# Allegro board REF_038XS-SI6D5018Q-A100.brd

Outline 581.66 x 429.26 mm; copper layers: TOP, L02_GND, L03_DPS, L04_GND, L05_DPS, L06_GND, L07_DPS, L08_GND, L09_DPS, L10_GND, L11_DPS, L12_GND, L13_SIGNAL, L14_GND, L15_SIGNAL, L16_GND, L17_SIGNAL, L18_GND, L19_SIGNAL, L20_GND, L21_SIGNAL, L22_GND, L23_SIGNAL, L24_GND, L25_SIGNAL, L26_GND, L27_SIGNAL, L28_GND, L29_SIGNAL, L30_GND, L31_SIGNAL, L32_GND, L33_SIGNAL, L34_GND, L35_DPS, L36_UDB, L37_GND, BOTTOM. Coordinates in mm from the lower left corner of the outline.

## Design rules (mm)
net group D231_MCB1_E: nets D231_MCB1_E+ D231_MCB1_E-
net group D231_MCB1_EE: nets D231_MCB1_EE+ D231_MCB1_EE-
net group D231_MCB1_F: nets D231_MCB1_F+ D231_MCB1_F-
net group D231_MCB1_FF: nets D231_MCB1_FF+ D231_MCB1_FF-
net group D231_MCB1_G: nets D231_MCB1_G+ D231_MCB1_G-
net group D231_MCB1_GG: nets D231_MCB1_GG+ D231_MCB1_GG-
net group D231_MCB1_H: nets D231_MCB1_H+ D231_MCB1_H-
net group D231_MCB1_HH: nets D231_MCB1_HH+ D231_MCB1_HH-
net group D232_MCB1_E: nets D232_MCB1_E+ D232_MCB1_E-
net group D232_MCB1_EE: nets D232_MCB1_EE+ D232_MCB1_EE-
net group D232_MCB1_F: nets D232_MCB1_F+ D232_MCB1_F-
net group D232_MCB1_FF: nets D232_MCB1_FF+ D232_MCB1_FF-
net group D232_MCB1_G: nets D232_MCB1_G+ D232_MCB1_G-
net group D232_MCB1_GG: nets D232_MCB1_GG+ D232_MCB1_GG-
net group D232_MCB1_H: nets D232_MCB1_H+ D232_MCB1_H-
net group D232_MCB1_HH: nets D232_MCB1_HH+ D232_MCB1_HH-
net group D431_MCB1_AA: nets D431_MCB1_AA+ D431_MCB1_AA-
net group D431_MCB1_BB: nets D431_MCB1_BB+ D431_MCB1_BB-
net group D431_MCB1_CC: nets D431_MCB1_CC+ D431_MCB1_CC-
net group D431_MCB1_DD: nets D431_MCB1_DD+ D431_MCB1_DD-
net group D432_MCB1_A: nets D432_MCB1_A+ D432_MCB1_A-
net group D432_MCB1_AA: nets D432_MCB1_AA+ D432_MCB1_AA-
net group D432_MCB1_B: nets D432_MCB1_B+ D432_MCB1_B-
net group D432_MCB1_BB: nets D432_MCB1_BB+ D432_MCB1_BB-
net group D432_MCB1_C: nets D432_MCB1_C+ D432_MCB1_C-
net group D432_MCB1_CC: nets D432_MCB1_CC+ D432_MCB1_CC-
net group D432_MCB1_D: nets D432_MCB1_D+ D432_MCB1_D-
net group D432_MCB1_DD: nets D432_MCB1_DD+ D432_MCB1_DD-
net group DIFFPAIR900: nets D21401 D21403
net group DIFFPAIR904: nets D10601 D10603
net group AWG: nets S1_AWG_2SHARE+ S1_AWG_2SHARE- S2_AWG_2SHARE+ S2_AWG_2SHARE- S3_AWG_2SHARE+ S3_AWG_2SHARE- S4_AWG_2SHARE+ S4_AWG_2SHARE- S5_AWG_2SHARE+ S5_AWG_2SHARE- S6_AWG_2SHARE+ S6_AWG_2SHARE- S7_AWG_2SHARE+ S7_AWG_2SHARE- S8_AWG_2SHARE+ S8_AWG_2SHARE-
net group ETH-1: nets D10907 D10909 D10912 D10914 D11307 D11309 D11312 D11314 D11708 D11710 D11711 D11713 D12108 D12110 D12111 D12113
net group ETH-2: nets D10905 D10910 D10911 D10916 D11305 D11310 D11311 D11316 D11706 D11709 D11712 D11715 D12106 D12109 D12112 D12115
net group ETH-3: nets D10906 D10908 D10913 D10915 D11306 D11308 D11313 D11315 D11705 D11707 D11714 D11716 D12105 D12107 D12114 D12116
net group MIPI1: nets D21601 D21603 D21901 D21903 D22109 D22111
net group MIPI2: nets D21602 D21604 D21902 D21904 D22110 D22112
net group MIPI3: nets D21605 D21607 D21905 D21907 D22113 D22115
net group MIPI4: nets D21606 D21608 D21906 D21908 D22114 D22116
net group MIPI5: nets D10801 D10803 D12009 D12011 D12901 D12903
net group MIPI6: nets D10802 D10804 D12010 D12012 D12902 D12904
net group MIPI7: nets D10805 D10807 D12013 D12015 D12905 D12907
net group MIPI8: nets D10806 D10808 D12014 D12016 D12906 D12908
net group MIPI SWITCH: nets S1_OUT_RX0_CH0_ABC_CASE+ S1_OUT_RX0_CH0_ABC_CASE- S1_OUT_RX0_CH1_ABC_CASE+ S1_OUT_RX0_CH1_ABC_CASE- S1_OUT_RX0_CH2_ABC_CASE+ S1_OUT_RX0_CH2_ABC_CASE-
net group MIPI SWITCH1: nets S2_OUT_RX0_CH0_ABC_CASE+ S2_OUT_RX0_CH0_ABC_CASE- S2_OUT_RX0_CH1_ABC_CASE+ S2_OUT_RX0_CH1_ABC_CASE- S2_OUT_RX0_CH2_ABC_CASE+ S2_OUT_RX0_CH2_ABC_CASE- S3_OUT_RX0_CH0_ABC_CASE+ S3_OUT_RX0_CH0_ABC_CASE- S3_OUT_RX0_CH1_ABC_CASE+ S3_OUT_RX0_CH1_ABC_CASE- S3_OUT_RX0_CH2_ABC_CASE+ S3_OUT_RX0_CH2_ABC_CASE- S4_OUT_RX0_CH0_ABC_CASE+ S4_OUT_RX0_CH0_ABC_CASE- S4_OUT_RX0_CH1_ABC_CASE+ S4_OUT_RX0_CH1_ABC_CASE- S4_OUT_RX0_CH2_ABC_CASE+ S4_OUT_RX0_CH2_ABC_CASE- S5_OUT_RX0_CH0_ABC_CASE+ S5_OUT_RX0_CH0_ABC_CASE- S5_OUT_RX0_CH1_ABC_CASE+ S5_OUT_RX0_CH1_ABC_CASE- S5_OUT_RX0_CH2_ABC_CASE+ S5_OUT_RX0_CH2_ABC_CASE- S6_OUT_RX0_CH0_ABC_CASE+ S6_OUT_RX0_CH0_ABC_CASE- S6_OUT_RX0_CH1_ABC_CASE+ S6_OUT_RX0_CH1_ABC_CASE- S6_OUT_RX0_CH2_ABC_CASE+ S6_OUT_RX0_CH2_ABC_CASE- S7_OUT_RX0_CH0_ABC_CASE+ S7_OUT_RX0_CH0_ABC_CASE- S7_OUT_RX0_CH1_ABC_CASE+ S7_OUT_RX0_CH1_ABC_CASE- S7_OUT_RX0_CH2_ABC_CASE+ S7_OUT_RX0_CH2_ABC_CASE- S8_OUT_RX0_CH0_ABC_CASE+ S8_OUT_RX0_CH0_ABC_CASE- S8_OUT_RX0_CH1_ABC_CASE+ S8_OUT_RX0_CH1_ABC_CASE- S8_OUT_RX0_CH2_ABC_CASE+ S8_OUT_RX0_CH2_ABC_CASE-

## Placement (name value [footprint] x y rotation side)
2SA1  SHORT  [DEFAULT_SHORT_SMALL]  265.71 251.64 180 top
2SA2  SHORT  [DEFAULT_SHORT_SMALL]  265.71 252.15 180 top
2SA7  SHORT  [DEFAULT_SHORT_SMALL]  264.03 245.86 90 top
2SA8  SHORT  [DEFAULT_SHORT_SMALL]  265.3 245.86 90 top
2SA9  SHORT  [DEFAULT_SHORT_SMALL]  266.07 238 180 top
2SA10  SHORT  [DEFAULT_SHORT_SMALL]  266.07 237.49 180 top
2SA15  SHORT  [DEFAULT_SHORT_SMALL]  277.49 250.16 90 top
2SA16  SHORT  [DEFAULT_SHORT_SMALL]  276.98 250.16 90 top
2SA17  SHORT  [DEFAULT_SHORT_SMALL]  273.21 238.53 0 top
2SA18  SHORT  [DEFAULT_SHORT_SMALL]  273.21 237.92 0 top
2SA19  SHORT  [DEFAULT_SHORT_SMALL]  264.08 243.68 270 top
2SA20  SHORT  [DEFAULT_SHORT_SMALL]  263.49 243.68 270 top
2SA21  SHORT  [DEFAULT_SHORT_SMALL]  279.27 250.18 90 top
2SA22  SHORT  [DEFAULT_SHORT_SMALL]  280.54 250.2 90 top
2SA23  SHORT  [DEFAULT_SHORT_SMALL]  273.41 237.52 270 top
2SA24  SHORT  [DEFAULT_SHORT_SMALL]  274.06 237.52 270 top
3SA1  SHORT  [DEFAULT_SHORT_SMALL]  305.71 251.64 180 top
3SA2  SHORT  [DEFAULT_SHORT_SMALL]  305.71 252.15 180 top
3SA7  SHORT  [DEFAULT_SHORT_SMALL]  304.03 245.86 90 top
3SA8  SHORT  [DEFAULT_SHORT_SMALL]  305.3 245.86 90 top
3SA9  SHORT  [DEFAULT_SHORT_SMALL]  306.07 238 180 top
3SA10  SHORT  [DEFAULT_SHORT_SMALL]  306.07 237.49 180 top
3SA15  SHORT  [DEFAULT_SHORT_SMALL]  317.49 250.16 90 top
3SA16  SHORT  [DEFAULT_SHORT_SMALL]  316.98 250.16 90 top
3SA17  SHORT  [DEFAULT_SHORT_SMALL]  313.21 238.53 0 top
3SA18  SHORT  [DEFAULT_SHORT_SMALL]  313.21 237.92 0 top
3SA19  SHORT  [DEFAULT_SHORT_SMALL]  304.08 243.68 270 top
3SA20  SHORT  [DEFAULT_SHORT_SMALL]  303.49 243.68 270 top
3SA21  SHORT  [DEFAULT_SHORT_SMALL]  319.27 250.18 90 top
3SA22  SHORT  [DEFAULT_SHORT_SMALL]  320.54 250.2 90 top
3SA23  SHORT  [DEFAULT_SHORT_SMALL]  313.41 237.52 270 top
3SA24  SHORT  [DEFAULT_SHORT_SMALL]  314.06 237.52 270 top
4SA1  SHORT  [DEFAULT_SHORT_SMALL]  345.71 251.64 180 top
4SA2  SHORT  [DEFAULT_SHORT_SMALL]  345.71 252.15 180 top
4SA7  SHORT  [DEFAULT_SHORT_SMALL]  344.03 245.86 90 top
4SA8  SHORT  [DEFAULT_SHORT_SMALL]  345.3 245.86 90 top
4SA9  SHORT  [DEFAULT_SHORT_SMALL]  346.07 238 180 top
4SA10  SHORT  [DEFAULT_SHORT_SMALL]  346.07 237.49 180 top
4SA15  SHORT  [DEFAULT_SHORT_SMALL]  357.49 250.16 90 top
4SA16  SHORT  [DEFAULT_SHORT_SMALL]  356.98 250.16 90 top
4SA17  SHORT  [DEFAULT_SHORT_SMALL]  353.21 238.53 0 top
4SA18  SHORT  [DEFAULT_SHORT_SMALL]  353.21 237.92 0 top
4SA19  SHORT  [DEFAULT_SHORT_SMALL]  344.08 243.68 270 top
4SA20  SHORT  [DEFAULT_SHORT_SMALL]  343.49 243.68 270 top
4SA21  SHORT  [DEFAULT_SHORT_SMALL]  359.27 250.18 90 top
4SA22  SHORT  [DEFAULT_SHORT_SMALL]  360.54 250.2 90 top
4SA23  SHORT  [DEFAULT_SHORT_SMALL]  353.41 237.52 270 top
4SA24  SHORT  [DEFAULT_SHORT_SMALL]  354.06 237.52 270 top
5SA1  SHORT  [DEFAULT_SHORT_SMALL]  236.06 191.36 0 top
5SA2  SHORT  [DEFAULT_SHORT_SMALL]  236.06 191.87 0 top
5SA7  SHORT  [DEFAULT_SHORT_SMALL]  223.4 185.16 90 top
5SA8  SHORT  [DEFAULT_SHORT_SMALL]  223.91 185.16 90 top
5SA9  SHORT  [DEFAULT_SHORT_SMALL]  234.24 174.5 270 top
5SA10  SHORT  [DEFAULT_SHORT_SMALL]  235.03 174.5 270 top
5SA15  SHORT  [DEFAULT_SHORT_SMALL]  239.49 193.83 90 top
5SA16  SHORT  [DEFAULT_SHORT_SMALL]  238.98 193.83 90 top
5SA17  SHORT  [DEFAULT_SHORT_SMALL]  235.98 191.77 0 top
5SA18  SHORT  [DEFAULT_SHORT_SMALL]  235.98 192.46 0 top
5SA19  SHORT  [DEFAULT_SHORT_SMALL]  224.08 183.68 270 top
5SA20  SHORT  [DEFAULT_SHORT_SMALL]  223.49 183.68 270 top
5SA21  SHORT  [DEFAULT_SHORT_SMALL]  234.54 193.95 0 top
5SA22  SHORT  [DEFAULT_SHORT_SMALL]  234.54 195.43 0 top
5SA23  SHORT  [DEFAULT_SHORT_SMALL]  233.04 174.51 270 top
5SA24  SHORT  [DEFAULT_SHORT_SMALL]  234.32 174.51 270 top
6SA1  SHORT  [DEFAULT_SHORT_SMALL]  276.06 191.36 0 top
6SA2  SHORT  [DEFAULT_SHORT_SMALL]  276.06 191.87 0 top
6SA7  SHORT  [DEFAULT_SHORT_SMALL]  263.4 185.16 90 top
6SA8  SHORT  [DEFAULT_SHORT_SMALL]  263.91 185.16 90 top
6SA9  SHORT  [DEFAULT_SHORT_SMALL]  274.24 174.5 270 top
6SA10  SHORT  [DEFAULT_SHORT_SMALL]  275.03 174.5 270 top
6SA15  SHORT  [DEFAULT_SHORT_SMALL]  279.49 193.83 90 top
6SA16  SHORT  [DEFAULT_SHORT_SMALL]  278.98 193.83 90 top
6SA17  SHORT  [DEFAULT_SHORT_SMALL]  275.98 191.77 0 top
6SA18  SHORT  [DEFAULT_SHORT_SMALL]  275.98 192.46 0 top
6SA19  SHORT  [DEFAULT_SHORT_SMALL]  264.08 183.68 270 top
6SA20  SHORT  [DEFAULT_SHORT_SMALL]  263.49 183.68 270 top
6SA21  SHORT  [DEFAULT_SHORT_SMALL]  274.54 193.95 0 top
6SA22  SHORT  [DEFAULT_SHORT_SMALL]  274.54 195.43 0 top
6SA23  SHORT  [DEFAULT_SHORT_SMALL]  273.04 174.51 270 top
6SA24  SHORT  [DEFAULT_SHORT_SMALL]  274.32 174.51 270 top
7SA1  SHORT  [DEFAULT_SHORT_SMALL]  316.06 191.36 0 top
7SA2  SHORT  [DEFAULT_SHORT_SMALL]  316.06 191.87 0 top
7SA7  SHORT  [DEFAULT_SHORT_SMALL]  303.4 185.16 90 top
7SA8  SHORT  [DEFAULT_SHORT_SMALL]  303.91 185.16 90 top
7SA9  SHORT  [DEFAULT_SHORT_SMALL]  314.24 174.5 270 top
7SA10  SHORT  [DEFAULT_SHORT_SMALL]  315.03 174.5 270 top
7SA15  SHORT  [DEFAULT_SHORT_SMALL]  319.49 193.83 90 top
7SA16  SHORT  [DEFAULT_SHORT_SMALL]  318.98 193.83 90 top
7SA17  SHORT  [DEFAULT_SHORT_SMALL]  315.98 191.77 0 top
7SA18  SHORT  [DEFAULT_SHORT_SMALL]  315.98 192.46 0 top
7SA19  SHORT  [DEFAULT_SHORT_SMALL]  304.08 183.68 270 top
7SA20  SHORT  [DEFAULT_SHORT_SMALL]  303.49 183.68 270 top
7SA21  SHORT  [DEFAULT_SHORT_SMALL]  314.54 193.95 0 top
7SA22  SHORT  [DEFAULT_SHORT_SMALL]  314.54 195.43 0 top
7SA23  SHORT  [DEFAULT_SHORT_SMALL]  313.04 174.51 270 top
7SA24  SHORT  [DEFAULT_SHORT_SMALL]  314.32 174.51 270 top
8SA1  SHORT  [DEFAULT_SHORT_SMALL]  356.06 191.36 0 top
8SA2  SHORT  [DEFAULT_SHORT_SMALL]  356.06 191.87 0 top
8SA7  SHORT  [DEFAULT_SHORT_SMALL]  343.4 185.16 90 top
8SA8  SHORT  [DEFAULT_SHORT_SMALL]  343.91 185.16 90 top
8SA9  SHORT  [DEFAULT_SHORT_SMALL]  354.24 174.5 270 top
8SA10  SHORT  [DEFAULT_SHORT_SMALL]  355.03 174.5 270 top
8SA15  SHORT  [DEFAULT_SHORT_SMALL]  359.49 193.83 90 top
8SA16  SHORT  [DEFAULT_SHORT_SMALL]  358.98 193.83 90 top
8SA17  SHORT  [DEFAULT_SHORT_SMALL]  355.98 191.77 0 top
8SA18  SHORT  [DEFAULT_SHORT_SMALL]  355.98 192.46 0 top
8SA19  SHORT  [DEFAULT_SHORT_SMALL]  344.08 183.68 270 top
8SA20  SHORT  [DEFAULT_SHORT_SMALL]  343.49 183.68 270 top
8SA21  SHORT  [DEFAULT_SHORT_SMALL]  354.54 193.95 0 top
8SA22  SHORT  [DEFAULT_SHORT_SMALL]  354.54 195.43 0 top
8SA23  SHORT  [DEFAULT_SHORT_SMALL]  353.04 174.51 270 top
8SA24  SHORT  [DEFAULT_SHORT_SMALL]  354.32 174.51 270 top
BD5  BD120-1.5A-S4-MU  [FB0402]  543.47 239.79 270 bottom
BD9  BD120-1.5A-S4-MU  [FB0402]  224.66 243.83 270 bottom
BD21  BD120-1.5A-S4-MU  [FB0402]  222.95 232.36 0 bottom
BD1721  BD120-1.5A-S4-MU  [FB0402]  543.47 226.84 270 bottom
BD1722  BD120-1.5A-S4-MU  [FB0402]  543.09 213.5 270 bottom
BD1723  BD120-1.5A-S4-MU  [FB0402]  543.09 199.41 270 bottom
BD1728  BD120-1.5A-S4-MU  [FB0402]  229.83 271.82 270 bottom
BD1729  BD120-1.5A-S4-MU  [FB0402]  236.97 270.94 270 bottom
BDB5  BD120-1.5A-S4-MU  [FB0402]  211.03 246.46 0 bottom
BDB6  BD120-1.5A-S4-MU  [FB0402]  211.03 234.89 0 bottom
BGA234-11X11-P0.65  REF-CODE-SOCKET  [SOCKET_CODE]  3.67 430.51 0 top
C262  0.1U-16-X7S-S2-MU  [C0201]  224.41 232.06 270 bottom
C264  NC/10U-16-X7R-S8-SS  [C0805]  227.48 269.95 90 bottom
C267  33P-50-N-S2-MU  [C0201]  236.23 224.18 270 bottom
C268  33P-50-N-S2-MU  [C0201]  235.23 224.18 270 bottom
C270  NC/10U-16-X7R-S8-SS  [C0805]  224.95 259 0 bottom
C271  12P-50-N-S4-MU  [C0402]  232.95 267.19 180 bottom
C272  12P-50-N-S4-MU  [C0402]  230.93 267.19 0 bottom
C278  1U-10-X7S-S4-TDK  [C0402]  232.87 289.3 0 bottom
C279  1U-10-X7S-S4-TDK  [C0402]  232.87 288.11 0 bottom
C280  0.1U-16-X-S4-MU  [C0402]  232.87 286.91 0 bottom
C281  0.1U-16-X-S4-MU  [C0402]  232.87 285.72 0 bottom
C282  1U-10-X7S-S4-TDK  [C0402]  238.7 282.67 270 bottom
C283  0.1U-16-X-S4-MU  [C0402]  237.54 282.67 270 bottom
C284  1U-10-X7S-S4-TDK  [C0402]  237.62 294.04 90 bottom
C285  0.1U-16-X-S4-MU  [C0402]  238.81 294.04 90 bottom
C286  0.1U-16-X-S4-MU  [C0402]  233.82 293.54 180 bottom
C288  1000P-50-X7R-S2-MU  [C0201]  233.49 291.76 270 bottom
C289  0.1U-16-X-S4-MU  [C0402]  231.21 291 270 bottom
C290  NC/0.1U-16-X7R-S4-TY  [C0402]  224.35 292.22 180 bottom
C298  0.1U-16-X7S-S2-MU  [C0201]  222.95 288.84 90 bottom
C299  0.1U-16-X7S-S2-MU  [C0201]  220.02 293.16 180 bottom
C300  0.1U-16-X-S4-MU  [C0402]  220.67 287.06 270 bottom
C301  1U-10-X7S-S4-TDK  [C0402]  219.51 287.06 270 bottom
C302  10P-50-N-S2-MU  [C0201]  214.98 243.61 0 bottom
C309  10P-50-N-S2-MU  [C0201]  214.98 255.18 0 bottom
C310  10P-50-N-S2-MU  [C0201]  213.69 255.18 180 bottom
C318  10P-50-N-S2-MU  [C0201]  211.94 255.18 0 bottom
C320  10P-50-N-S2-MU  [C0201]  213.69 243.61 180 bottom
C332  2.2U-16-X7R-S6-TY  [C0603]  109.1 226.65 270 bottom
C333  0.1U-16-X-S4-MU  [C0402]  107.7 226.83 270 bottom
C334  10U-16-X7R-S8-SS  [C0805]  100.08 226.53 90 bottom
C335  0.1U-16-X-S4-MU  [C0402]  101.74 226.35 90 bottom
C336  4.7U-25-X7R-S8-TY  [C0805]  87.58 240.29 270 bottom
C337  0.1U-16-X-S4-MU  [C0402]  87.6 237.74 180 bottom
C338  4.7U-25-X7R-S8-TY  [C0805]  106 240.29 270 bottom
C339  0.1U-16-X-S4-MU  [C0402]  106.03 237.74 180 bottom
C400  2.2U-10-X-S4-MU  [C0402]  540.94 239.82 90 bottom
C401  0.1U-16-X-S4-MU  [C0402]  542.2 239.82 90 bottom
C402  4.7U-6.3-X-S4-MU  [C0402]  523.51 152.12 0 bottom
C403  22U-16-X5R-SA-SS  [C1206]  520.12 149.58 90 bottom
C404  10U-25-X-S6-MU  [C0603]  519.86 146.58 180 bottom
C405  1U-10-X7S-S4-TDK  [C0402]  520.37 145.26 180 bottom
C406  0.1U-16-X-S4-MU  [C0402]  90.42 287.53 180 bottom
C407  2.2U-10-X-S4-MU  [C0402]  82.6 288.09 270 bottom
C408  0.1U-16-X-S4-MU  [C0402]  83.74 288.09 270 bottom
C409  0.1U-16-X-S4-MU  [C0402]  73.71 296.14 0 bottom
C410  0.1U-16-X-S4-MU  [C0402]  503.58 221.92 270 bottom
C411  0.1U-16-X-S4-MU  [C0402]  493.55 229.97 0 bottom
C412  2.2U-10-X-S4-MU  [C0402]  502.43 221.92 270 bottom
C413  0.1U-16-X-S4-MU  [C0402]  510.25 221.35 180 bottom
C415  0.1U-16-X-S4-MU  [C0402]  90.42 273.81 180 bottom
C416  2.2U-10-X-S4-MU  [C0402]  82.6 274.38 270 bottom
C417  0.1U-16-X-S4-MU  [C0402]  73.71 282.43 0 bottom
C475  4.7U-6.3-X-S4-MU  [C0402]  225.86 265.11 270 bottom
C476  1U-10-X7S-S4-TDK  [C0402]  219 268.25 90 bottom
C477  10U-25-X-S6-MU  [C0603]  220.32 268.76 90 bottom
C478  22U-16-X5R-SA-SS  [C1206]  223.32 268.5 0 bottom
C894  0.1U-16-X-S4-MU  [C0402]  542.2 226.87 90 bottom
C895  2.2U-10-X-S4-MU  [C0402]  540.94 226.87 90 bottom
C910  0.1U-16-X-S4-MU  [C0402]  83.74 274.38 270 bottom
C922  0.1U-16-X-S4-MU  [C0402]  213.16 246.46 0 bottom
C923  0.1U-16-X-S4-MU  [C0402]  213.16 234.89 0 bottom
C924  10P-50-N-S2-MU  [C0201]  211.94 243.61 0 bottom
C955  0.1U-16-X-S4-MU  [C0402]  90.42 260.1 180 bottom
C956  2.2U-10-X-S4-MU  [C0402]  82.6 260.66 270 bottom
C957  0.1U-16-X-S4-MU  [C0402]  73.71 268.71 0 bottom
C958  0.1U-16-X-S4-MU  [C0402]  83.74 260.66 270 bottom
C983  0.1U-16-X-S4-MU  [C0402]  541.82 213.53 90 bottom
C984  2.2U-10-X-S4-MU  [C0402]  540.55 213.53 90 bottom
C985  0.1U-16-X-S4-MU  [C0402]  541.82 199.44 90 bottom
C986  2.2U-10-X-S4-MU  [C0402]  540.55 199.44 90 bottom
C1066  0.01U-10-X7R-S2-YA  [C0201]  244.98 274.19 0 bottom
C1067  0.01U-10-X7R-S2-YA  [C0201]  246.33 274.19 180 bottom
C1074  0.1U-16-X7S-S2-MU  [C0201_MINI]  229.58 270.27 180 bottom
C1077  0.1U-16-X7S-S2-MU  [C0201_MINI]  236.72 269.49 180 bottom
C1080  0.1U-16-X7S-S2-MU  [C0201_MINI]  242.99 269.49 180 bottom
C1081  0.1U-16-X7S-S2-MU  [C0201_MINI]  243.8 273.3 180 bottom
C1082  0.1U-16-X-S4-MU  [C0402]  503.58 203.76 270 bottom
C1083  0.1U-16-X-S4-MU  [C0402]  248.15 224.79 0 bottom
C1085  2.2U-10-X-S4-MU  [C0402]  493.55 211.81 0 bottom
CA1  0.1U-16-X-S4-MU  [C0402]  205.72 237.49 0 bottom
CA2  10U-25-X7R-SA  [C1206]  205.72 240.03 0 bottom
CA7  10U-25-X7R-SA  [C1206]  245.12 281.69 0 bottom
CA8  0.1U-16-X-S4-MU  [C0402]  245.12 279.65 0 bottom
CA19  470U-25-E-S10.4X10.4  [EC_10P3X10_S]  189.66 230.89 90 bottom
CA20  10U-25-X7R-SA  [C1206]  216.67 281.69 0 bottom
CA21  0.1U-16-X-S4-MU  [C0402]  216.67 279.65 0 bottom
CA22  10U-25-X7R-SA  [C1206]  222.76 277.62 0 bottom
CA23  0.1U-16-X-S4-MU  [C0402]  222.76 275.59 0 bottom
CA24  10U-25-X7R-SA  [C1206]  216.67 277.62 0 bottom
CA25  0.1U-16-X-S4-MU  [C0402]  216.67 275.59 0 bottom
CA26  10U-25-X7R-SA  [C1206]  235.18 277.62 0 bottom
CA27  0.1U-16-X-S4-MU  [C0402]  235.18 275.59 0 bottom
CA34  10U-25-X7R-SA  [C1206]  245.12 277.62 0 bottom
CA35  0.1U-16-X-S4-MU  [C0402]  245.12 275.59 0 bottom
CA36  0.1U-16-X-S4-MU  [C0402]  228.85 275.59 0 bottom
CA37  10U-25-X7R-SA  [C1206]  228.85 277.62 0 bottom
CB1  0.1U-25-X-S6  [C0603]  416.81 133.35 0 bottom
CB2  10U-25-X7R-SA  [C1206]  416.81 130.81 0 bottom
CB3  0.1U-25-X-S6  [C0603]  560.07 133.35 0 bottom
CB4  10U-25-X7R-SA  [C1206]  560.07 130.81 0 bottom
CB5  0.1U-25-X-S6  [C0603]  560.07 295.91 180 bottom
CB6  10U-25-X7R-SA  [C1206]  560.07 298.45 180 bottom
CB7  0.1U-25-X-S6  [C0603]  424.16 290.83 180 bottom
CB8  10U-25-X7R-SA  [C1206]  424.16 293.37 180 bottom
CB9  0.1U-25-X-S6  [C0603]  164.85 133.35 0 bottom
CB10  10U-25-X7R-SA  [C1206]  164.85 130.81 0 bottom
CB11  0.1U-25-X-S6  [C0603]  157.46 290.83 180 bottom
CB12  10U-25-X7R-SA  [C1206]  157.46 293.37 180 bottom
CB13  0.1U-25-X-S6  [C0603]  21.59 133.35 0 bottom
CB14  10U-25-X7R-SA  [C1206]  21.59 130.81 0 bottom
CB15  0.1U-25-X-S6  [C0603]  21.59 295.91 180 bottom
CB16  10U-25-X7R-SA  [C1206]  21.59 298.45 180 bottom
CC1  0.1U-16-X7S-S2-MU  [C0201]  230.19 246.91 180 bottom
CC2  0.1U-16-X7S-S2-MU  [C0201]  230.5 250.48 90 bottom
CC3  0.1U-16-X7S-S2-MU  [C0201]  228.87 245.61 180 bottom
CC4  0.1U-16-X7S-S2-MU  [C0201]  230.19 246.26 180 bottom
CC5  0.1U-16-X7S-S2-MU  [C0201]  231.16 246.56 90 bottom
CC6  0.1U-16-X7S-S2-MU  [C0201]  228.87 244.96 180 bottom
CC7  0.1U-16-X7S-S2-MU  [C0201]  232.14 244.96 0 bottom
CC8  0.1U-16-X7S-S2-MU  [C0201]  230.5 243.97 270 bottom
CC9  0.1U-16-X7S-S2-MU  [C0201]  231.16 243.97 270 bottom
CC12  0.1U-16-X7S-S2-MU  [C0201]  229.86 244.62 270 bottom
CC13  0.1U-16-X7S-S2-MU  [C0201]  228.24 241.05 180 bottom
CC14  0.1U-16-X7S-S2-MU  [C0201]  231.46 245.61 0 bottom
CC15  0.1U-16-X7S-S2-MU  [C0201]  230.19 245.61 180 bottom
CC16  0.1U-16-X7S-S2-MU  [C0201]  230.84 244.96 180 bottom
CC70  0.1U-16-X7S-S2-MU  [C0201]  232.46 242.67 270 bottom
CC71  0.1U-16-X7S-S2-MU  [C0201]  235.38 243 0 bottom
CC73  0.1U-16-X7S-S2-MU  [C0201]  227.91 242.68 90 bottom
CC84  0.1U-16-X7S-S2-MU  [C0201]  233.11 250.48 90 bottom
CC85  0.1U-16-X7S-S2-MU  [C0201]  231.15 250.48 90 bottom
CC86  0.1U-16-X7S-S2-MU  [C0201]  232.46 250.48 90 bottom
CC87  0.1U-16-X7S-S2-MU  [C0201]  232.14 246.26 180 bottom
CC88  0.1U-16-X7S-S2-MU  [C0201]  233.11 244 270 bottom
CC89  0.1U-16-X7S-S2-MU  [C0201]  227.91 244.66 270 bottom
CC90  0.1U-16-X7S-S2-MU  [C0201]  231.8 250.48 90 bottom
CC91  0.1U-16-X7S-S2-MU  [C0201]  234.06 243.65 0 bottom
CC92  0.1U-16-X7S-S2-MU  [C0201]  232.45 244 270 bottom
CC96  0.1U-16-X7S-S2-MU  [C0201]  231.51 247.56 180 bottom
CC101  0.1U-16-X7S-S2-MU  [C0201]  230.84 240.4 0 bottom
CC103  0.1U-16-X7S-S2-MU  [C0201]  231.81 242.02 90 bottom
CC105  0.1U-16-X7S-S2-MU  [C0201]  232.46 240.72 270 bottom
CC107  0.1U-16-X7S-S2-MU  [C0201]  232.76 241.7 0 bottom
CC112  0.1U-16-X7S-S2-MU  [C0201]  235.06 250.48 90 bottom
CC130  0.1U-16-X7S-S2-MU  [C0201]  228.24 241.7 180 bottom
CC133  1U-6.3-X7T-S2-MU  [C0201]  227.26 238.78 270 bottom
CC134  NC/0.1U-10-X7R-S2-MU  [C0201]  227.91 238.78 270 bottom
CC182  0.1U-16-X7S-S2-MU  [C0201]  226.61 250.48 90 bottom
CC194  0.1U-16-X7S-S2-MU  [C0201]  231.49 243 180 bottom
CC202  0.1U-16-X7S-S2-MU  [C0201]  226.28 245.61 180 bottom
CC203  0.1U-16-X7S-S2-MU  [C0201]  229.86 239.42 270 bottom
CC204  0.1U-16-X7S-S2-MU  [C0201]  230.51 239.42 270 bottom
CC205  0.1U-16-X7S-S2-MU  [C0201]  231.16 239.42 270 bottom
CC208  0.1U-16-X7S-S2-MU  [C0201]  227.57 246.26 180 bottom
CC209  0.1U-16-X7S-S2-MU  [C0201]  228.23 247.56 180 bottom
CC210  0.1U-16-X7S-S2-MU  [C0201]  229.53 240.41 180 bottom
CC211  0.1U-16-X7S-S2-MU  [C0201]  230.5 242.02 90 bottom
CC212  0.1U-16-X7S-S2-MU  [C0201]  229.53 241.06 180 bottom
CC213  0.1U-16-X7S-S2-MU  [C0201]  231.16 242.02 90 bottom
CC215  0.1U-16-X7S-S2-MU  [C0201]  231.81 239.42 90 bottom
CC216  0.1U-16-X7S-S2-MU  [C0201]  228.56 238.78 270 bottom
CD1  0.1U-16-X7S-S2-MU  [C0201]  295.73 296.3 90 top
CD2  0.1U-16-X7S-S2-MU  [C0201]  465.17 278.08 90 top
CON1  MS-PWR-CONN-30P-V3-SI6D70  [CONN_15X2_100MIL_PH_MS_V2]  24.74 150.36 90 top
CSDPS303  V93K_CSDPS_DPS32  [PG_VG93K_PF_DPS32_G1D303]  327.66 46.99 0 top
CSDPS307  V93K_CSDPS_DPS32  [PG_VG93K_PF_DPS32_G1D307]  401.32 46.99 0 top
CSDPS310  V93K_CSDPS_DPS32  [PG_VG93K_PF_DPS32_G2D310]  401.32 361.95 0 top
CSDPS314  V93K_CSDPS_DPS32  [PG_VG93K_PF_DPS32_G2D314]  327.66 361.95 0 top
CSDPS319  V93K_CSDPS_DPS32  [PG_VG93K_PF_DPS32_G3D319]  180.34 46.99 0 top
CSDPS323  V93K_CSDPS_DPS32  [PG_VG93K_PF_DPS32_G3D323]  254 46.99 0 top
CSDPS426  V93K_CSDPS  [PG_VG93K_PF_DPS32_G8D426]  254 361.95 0 top
CSDPS430  V93K_CSDPS  [PG_VG93K_PF_DPS32_G8D430]  180.34 361.95 0 top
D101  V93K_CH  [PG_VG93K_F_G1D101]  327.66 97.79 0 top
D102  V93K_CH  [PG_VG93K_F_G1D102]  327.66 77.47 0 top
D103  V93K_CH  [PG_VG93K_F_G1D103]  327.66 57.15 0 top
D104  V93K_CH  [PG_VG93K_F_G1D104]  327.66 36.83 0 top
D105  V93K_CH  [PG_VG93K_F_G1D105]  401.32 97.79 0 top
D106  V93K_CH  [PG_VG93K_F_G1D106]  401.32 77.47 0 top
D107  V93K_CH  [PG_VG93K_F_G1D107]  401.32 57.15 0 top
D108  V93K_CH  [PG_VG93K_F_G1D108]  401.32 36.83 0 top
D109  V93K_CH  [PG_VG93K_F_G2D109]  401.32 331.47 0 top
D110  V93K_CH  [PG_VG93K_F_G2D110]  401.32 351.79 0 top
D111  V93K_CH  [PG_VG93K_F_G2D111]  401.32 372.11 0 top
D112  V93K_CH  [PG_VG93K_F_G2D112]  401.32 392.43 0 top
D113  V93K_CH  [PG_VG93K_F_G2D113]  327.66 331.47 0 top
D114  V93K_CH  [PG_VG93K_F_G2D114]  327.66 351.79 0 top
D115  V93K_CH  [PG_VG93K_F_G2D115]  327.66 372.11 0 top
D116  V93K_CH  [PG_VG93K_F_G2D116]  327.66 392.43 0 top
D117  V93K_CH  [PG_VG93K_F_G3D117]  180.34 97.79 0 top
D118  V93K_CH  [PG_VG93K_F_G3D118]  180.34 77.47 0 top
D119  V93K_CH  [PG_VG93K_F_G3D119]  180.34 57.15 0 top
D120  V93K_CH  [PG_VG93K_F_G3D120]  180.34 36.83 0 top
D121  V93K_CH  [PG_VG93K_F_G3D121]  254 97.79 0 top
D122  V93K_CH  [PG_VG93K_F_G3D122]  254 77.47 0 top
D123  V93K_CH  [PG_VG93K_F_G3D123]  254 57.15 0 top
D124  V93K_CH  [PG_VG93K_F_G3D124]  254 36.83 0 top
D125  V93K_CH  [PG_VG93K_F_G4D125]  33.02 97.79 0 top
D126  V93K_CH  [PG_VG93K_F_G4D126]  33.02 77.47 0 top
D127  V93K_CH  [PG_VG93K_F_G4D127]  33.02 57.15 0 top
D128  V93K_CH  [PG_VG93K_F_G4D128]  33.02 36.83 0 top
D129  V93K_CH  [PG_VG93K_F_G4D129]  106.68 97.79 0 top
D130  V93K_CH  [PG_VG93K_F_G4D130]  106.68 77.47 0 top
D131  V93K_CH  [PG_VG93K_F_G4D131]  106.68 57.15 0 top
D132  V93K_CH  [PG_VG93K_F_G4D132]  106.68 36.83 0 top
D201  V93K_CH  [PG_VG93K_F_G5D201]  474.98 97.79 0 top
D202  V93K_CH  [PG_VG93K_F_G5D202]  474.98 77.47 0 top
D203  V93K_CH  [PG_VG93K_F_G5D203]  474.98 57.15 0 top
D204  V93K_CH  [PG_VG93K_F_G5D204]  474.98 36.83 0 top
D205  V93K_CH  [PG_VG93K_F_G5D205]  548.64 97.79 0 top
D206  V93K_CH  [PG_VG93K_F_G5D206]  548.64 77.47 0 top
D207  V93K_CH  [PG_VG93K_F_G5D207]  548.64 57.15 0 top
D208  V93K_CH  [PG_VG93K_F_G5D208]  548.64 36.83 0 top
D209  V93K_CH  [PG_VG93K_F_G6D209]  548.64 331.47 0 top
D210  V93K_CH  [PG_VG93K_F_G6D210]  548.64 351.79 0 top
D211  V93K_CH  [PG_VG93K_F_G6D211]  548.64 372.11 0 top
D212  V93K_CH  [PG_VG93K_F_G6D212]  548.64 392.43 0 top
D213  V93K_CH  [PG_VG93K_F_G6D213]  474.98 331.47 0 top
D214  V93K_CH  [PG_VG93K_F_G6D214]  474.98 351.79 0 top
D215  V93K_CH  [PG_VG93K_F_G6D215]  474.98 372.11 0 top
D216  V93K_CH  [PG_VG93K_F_G6D216]  474.98 392.43 0 top
D217  V93K_CH  [PG_VG93K_F_G7D217]  106.68 331.47 0 top
D218  V93K_CH  [PG_VG93K_F_G7D218]  106.68 351.79 0 top
D219  V93K_CH  [PG_VG93K_F_G7D219]  106.68 372.11 0 top
D220  V93K_CH  [PG_VG93K_F_G7D220]  106.68 392.43 0 top
D221  V93K_CH  [PG_VG93K_F_G7D221]  33.02 331.47 0 top
D222  V93K_CH  [PG_VG93K_F_G7D222]  33.02 351.79 0 top
D223  V93K_CH  [PG_VG93K_F_G7D223]  33.02 372.11 0 top
D224  V93K_CH  [PG_VG93K_F_G7D224]  33.02 392.43 0 top
D225  V93K_CH_ND  [PG_VG93K_F_G8D225_ND]  254 331.47 0 top
D226/D626  V93K_PS1600 HD  [PG_VG93K_F_HSM_G8D226_626_ND]  254 351.79 0 top
D227  V93K_CH  [PG_VG93K_F_G8D227]  254 372.11 0 top
D228  V93K_CH  [PG_VG93K_F_G8D228]  254 392.43 0 top
D229  V93K_CH_ND  [PG_VG93K_F_G8D229_ND]  180.34 331.47 0 top
D230/D630  V93K_PS1600 HD  [PG_VG93K_F_HSM_G8D230_630_ND]  180.34 351.79 0 top
D231  V93K_CH  [PG_VG93K_F_G8D231]  180.34 372.11 0 top
D232  V93K_CH  [PG_VG93K_F_G8D232]  180.34 392.43 0 top
D325  V93K_CH  [PG_VG93K_F_G4D325]  33.02 87.63 0 top
D326  V93K_CH  [PG_VG93K_F_G4D326]  33.02 67.31 0 top
D327  V93K_CH  [PG_VG93K_F_G4D327]  33.02 46.99 0 top
D328  V93K_CH  [PG_VG93K_F_G4D328]  33.02 26.67 0 top
D329  V93K_CH  [PG_VG93K_F_G4D329]  106.68 87.63 0 top
D330  V93K_CH  [PG_VG93K_F_G4D330]  106.68 67.31 0 top
D331  V93K_CH  [PG_VG93K_F_G4D331]  106.68 46.99 0 top
D332  V93K_CH  [PG_VG93K_F_G4D332]  106.68 26.67 0 top
D409  V93K_CH  [PG_VG93K_F_G6D409]  548.64 341.63 0 top
D410  V93K_CH  [PG_VG93K_F_G6D410]  548.64 361.95 0 top
D411  V93K_CH  [PG_VG93K_F_G6D411]  548.64 382.27 0 top
D412  V93K_CH  [PG_VG93K_F_G6D412]  548.64 402.59 0 top
D413  V93K_CH  [PG_VG93K_F_G6D413]  474.98 341.63 0 top
D414  V93K_CH  [PG_VG93K_F_G6D414]  474.98 361.95 0 top
D415  V93K_CH  [PG_VG93K_F_G6D415]  474.98 382.27 0 top
D416  V93K_CH  [PG_VG93K_F_G6D416]  474.98 402.59 0 top
D417  V93K_CH  [PG_VG93K_F_G7D417]  106.68 341.63 0 top
D418  V93K_CH  [PG_VG93K_F_G7D418]  106.68 361.95 0 top
D419  V93K_CH  [PG_VG93K_F_G7D419]  106.68 382.27 0 top
D420  V93K_CH  [PG_VG93K_F_G7D420]  106.68 402.59 0 top
D421  V93K_CH  [PG_VG93K_F_G7D421]  33.02 341.63 0 top
D422  V93K_CH  [PG_VG93K_F_G7D422]  33.02 361.95 0 top
D423  V93K_CH  [PG_VG93K_F_G7D423]  33.02 382.27 0 top
D424  V93K_CH  [PG_VG93K_F_G7D424]  33.02 402.59 0 top
D425  V93K_CH_ND  [PG_VG93K_F_G8D425_ND]  254 341.63 0 top
D427  V93K_CH  [PG_VG93K_F_G8D427]  254 382.27 0 top
D428  V93K_CH  [PG_VG93K_F_G8D428]  254 402.59 0 top
D429  V93K_CH_ND  [PG_VG93K_F_G8D429_ND]  180.34 341.63 0 top
D431  V93K_CH  [PG_VG93K_F_G8D431]  180.34 382.27 0 top
D432  V93K_CH  [PG_VG93K_F_G8D432]  180.34 402.59 0 top
DPS1  V93K_DPS  [PG_VG93K_F_G1DPS1]  401.32 16.51 0 top
DPS2  V93K_DPS  [PG_VG93K_F_G2DPS2]  327.66 412.75 0 top
DPS3  V93K_DPS  [PG_VG93K_F_G3DPS3]  254 16.51 0 top
DPS8  V93K_DPS  [PG_VG93K_F_G8DPS8]  180.34 412.75 0 top
FD1  -  [FD_040_V2]  10.16 129.54 0 top
FD2  -  [FD_040_V2]  11.43 298.45 0 top
FD3  -  [FD_040_V2]  157.48 298.45 0 top
FD4  -  [FD_040_V2]  157.48 130.81 0 top
FD5  -  [FD_040_V2]  424.18 298.45 0 top
FD6  -  [FD_040_V2]  424.18 130.81 0 top
FD7  -  [FD_040_V2]  570.23 298.45 0 top
FD8  -  [FD_040_V2]  570.23 130.81 0 top
FD9  -  [FD_040_V2]  10.16 129.54 180 bottom
FD10  -  [FD_040_V2]  11.43 298.45 180 bottom
FD11  -  [FD_040_V2]  157.48 298.45 180 bottom
FD12  -  [FD_040_V2]  157.48 130.81 180 bottom
FD13  -  [FD_040_V2]  424.18 298.45 180 bottom
FD14  -  [FD_040_V2]  424.18 130.81 180 bottom
FD15  -  [FD_040_V2]  570.23 298.45 180 bottom
FD16  -  [FD_040_V2]  570.23 130.81 180 bottom
H1  M3-HOLE  [M3_NPTH169]  158.75 241.3 0 top
H2  M3-HOLE  [M3_NPTH169]  158.75 187.96 0 top
H3  M3-HOLE  [M3_NPTH169]  422.91 241.3 0 top
H4  M3-HOLE  [M3_NPTH169]  422.91 187.96 0 top
J1  HDR-2X1-M  [JP_2P_100]  10.78 152.9 180 top
J2  HDR-2X1-M  [JP_2P_100]  14.16 152.9 180 top
JP1  A2001WV0-4PS  [CONN_S4X1_2MM_JWT]  100.37 260.08 90 top
K2  UA2-5NJ-A-V3  [RL_NECUA2_5V_V3]  119.04 248.1 90 bottom
K3  UA2-5NJ-A-V3  [RL_NECUA2_5V_V3]  112.69 248.1 90 bottom
K4  UA2-5NJ-A-V3  [RL_NECUA2_5V_V3]  106.34 248.1 90 bottom
K5  UA2-5NJ-A-V3  [RL_NECUA2_5V_V3]  99.99 248.1 90 bottom
K6  UA2-5NJ-A-V3  [RL_NECUA2_5V_V3]  93.64 248.1 90 bottom
K7  UA2-5NJ-A-V3  [RL_NECUA2_5V_V3]  87.29 248.1 90 bottom
K29  G6K-2F-Y-5V-A  [RL_G6K2F-Y_5V_OMRON]  231.94 258.56 90 bottom
K32  G6K-2F-Y-5V-A  [RL_G6K2F-Y_5V_OMRON]  235.73 231.79 270 bottom
K34  G6K-2P-Y5VDC-A  [RL_OMRONG6K2PY_5V]  166.88 269.24 90 bottom
K39  UA2-5NE-A-V3  [RL_NECUA2_5V_V3]  224.66 224.54 180 bottom
K96  EC2-5NJ  [RL_NECEC2_10P_5V]  203.76 229.39 0 bottom
K107  G6K-2P-Y5VDC-A  [RL_OMRONG6K2PY_5V]  166.88 281.43 90 bottom
K109  G6K-2P-Y5VDC-A  [RL_OMRONG6K2PY_5V]  166.88 293.62 90 bottom
K110  G6K-2P-Y5VDC-A  [RL_OMRONG6K2PY_5V]  176.53 293.62 90 bottom
K111  G6K-2P-Y5VDC-A  [RL_OMRONG6K2PY_5V]  186.18 293.62 90 bottom
K112  G6K-2P-Y5VDC-A  [RL_OMRONG6K2PY_5V]  195.83 293.62 90 bottom
K113  MFS-E1T05G-A  [RL_MFS-E1T-G_5V]  245.11 221.36 0 bottom
LDB1  LDG-2-S8  [LED_0805]  40.96 298.45 0 top
LOGO1  LOGO_SR_SigmaStar  [LOGO_SR_SIGMASTAR]  29.16 434.98 0 top
LOGO2  -  [LOGO_KT_KSMT]  81.21 434.37 0 top
LRB1  330-1-S6  [R0603]  42.89 298.45 180 bottom
MBD1  BD120-1.5A-S4-MU  [FB0402]  222.95 290.49 270 bottom
MK1  AQY221R2MY-V2  [RL_AQY221R2MY_5V_V2]  225.87 284.52 180 bottom
MK2  AQY221R2MY-V2  [RL_AQY221R2MY_5V_V2]  225.87 289.86 180 bottom
MK3  AQY221R2MY-V2  [RL_AQY221R2MY_5V_V2]  225.87 281.98 180 bottom
MK4  AQY221R2MY-V2  [RL_AQY221R2MY_5V_V2]  225.87 287.19 180 bottom
MR1  1M-1-S4  [R0402_UNBGA_V2]  236.22 282.67 270 bottom
MR2  1K-0.01-S4  [R0402_UNBGA_V2]  235.91 293.54 180 bottom
MR3  1K-0.01-S4  [R0402_UNBGA_V2]  233.82 294.56 180 bottom
MR4  1K-0.01-S4  [R0402_UNBGA_V2]  233.82 295.57 180 bottom
MR5  1K-0.01-S4  [R0402_UNBGA_V2]  235.91 295.57 0 bottom
MR6  1K-0.01-S4  [R0402_UNBGA_V2]  235.91 294.56 0 bottom
MR7  332K-1-S4  [R0402_UNBGA_V2]  235.21 281.82 90 bottom
MR8  1K-0.01-S4  [R0402_UNBGA_V2]  224.35 295.57 180 bottom
MR9  499-0.1-S4  [R0402]  224.35 294.46 180 bottom
MR10  0-5-S4  [R0402]  224.35 293.34 0 bottom
MR11  750-1-S4  [R0402]  229.3 285.16 180 bottom
MR12  360-1-S6  [R0603]  229.68 283.89 180 bottom
MR13  750-1-S4  [R0402]  229.3 290.49 180 bottom
MR14  1.2K-1-S4  [R0402]  229.05 282.62 0 bottom
MR15  360-1-S6  [R0603]  229.68 289.22 180 bottom
MR16  750-1-S4  [R0402]  229.3 287.83 180 bottom
MR17  360-1-S6  [R0603]  229.68 286.56 180 bottom
MR18  11K-0.1-S4  [R0402]  221.81 287.06 270 bottom
MR19  1K-0.01-S4  [R0402_UNBGA_V2]  222.95 287.06 90 bottom
MU1  KSMT002-0.15A-A-SC70-5  [SC70_5P]  233.15 283.82 90 bottom
MU2  KSMT004-SO8  [SO8_244X127MM]  238.06 288.21 90 bottom
MU3  KSMT003-MSOP8  [SO8_172X0P65MM]  228.92 293.67 180 bottom
MU4  MAX6070AAUT30+T-SOT23  [SOT23_6P_0P95X2P7MM_H1P45MM]  220.67 290.49 0 bottom
NOREF  -  []  305.98 185.61 0 top
NOREF#2  -  []  109.69 158.1 0 top
NOREF#3  -  []  263.27 233.14 0 top
NOREF#4  -  []  269.89 246.91 0 top
NOREF#5  -  []  547.34 222.67 0 top
NOREF#6  -  []  335.58 183.29 90 top
NOREF#7  -  []  230.57 208.63 0 top
NOREF#8  -  []  367.4 207.92 90 top
NOREF#9  -  []  533.93 205.02 0 top
NOREF#10  -  []  503.03 205.98 90 top
NOREF#11  -  []  295.01 182 90 top
NOREF#12  -  []  85.49 249.7 0 top
NOREF#13  -  []  534.31 218.36 0 top
NOREF#14  -  []  308.66 166.14 0 top
NOREF#15  -  []  350.18 243.37 90 top
NOREF#16  -  []  352.13 180.12 90 top
NOREF#17  -  []  102.08 170.76 0 top
NOREF#18  -  []  364.05 212.03 90 top
NOREF#19  -  []  227.64 180.73 90 top
NOREF#20  -  []  352.74 244.64 90 top
NOREF#21  -  []  270.5 250.18 90 top
NOREF#22  -  []  109.69 253.35 0 top
NOREF#23  -  []  334.68 253.86 90 top
NOREF#24  -  []  291.31 243.2 0 top
NOREF#25  -  []  227.63 247.88 0 top
NOREF#26  -  []  225.88 235.27 0 top
NOREF#27  -  []  276.94 192.76 90 top
NOREF#28  -  []  535.51 231.31 90 top
NOREF#29  -  []  269.85 239.12 90 top
NOREF#30  -  []  310.18 183.37 90 top
NOREF#31  -  []  474.45 217.95 0 top
NOREF#32  -  []  273.46 183.33 0 top
NOREF#33  -  []  235.44 194.76 90 top
NOREF#34  -  []  266.97 186.58 0 top
NOREF#35  -  []  271.16 183.67 90 top
NOREF#36  -  []  558.12 164.49 0 top
NOREF#37  -  []  344.96 134.08 0 top
NOREF#38  -  []  309.5 208.8 90 top
NOREF#39  -  []  275.44 194.76 90 top
NOREF#40  -  []  316.65 207.92 0 top
NOREF#41  -  []  307.05 133.3 90 top
NOREF#42  -  []  308.23 178.18 90 top
NOREF#43  -  []  310.73 226.09 90 top
NOREF#44  -  []  351.48 191.08 0 top
NOREF#45  -  []  307.64 181.38 0 top
NOREF#46  -  []  314.65 243.33 90 top
NOREF#47  -  []  253.61 253.56 90 top
NOREF#48  -  []  348.25 233.12 90 top
NOREF#49  -  []  227.59 238.18 90 top
NOREF#50  -  []  331.83 263.63 0 top
NOREF#51  -  []  254.36 183.2 0 top
NOREF#52  -  []  350.73 226.09 90 top
NOREF#53  -  []  83.8 289.54 90 top
NOREF#54  -  []  262.95 286.63 90 top
NOREF#55  -  []  236.29 269.25 90 top
NOREF#56  -  []  78.8 276.65 0 top
NOREF#57  -  []  307.25 178.48 90 top
NOREF#58  -  []  276.23 134 90 top
NOREF#59  -  []  293.99 182.3 90 top
NOREF#60  -  []  215.16 191.22 90 top
NOREF#61  -  []  292.66 182 90 top
NOREF#62  -  []  232.14 242.07 0 top
NOREF#63  -  []  312.46 181.7 0 top
NOREF#64  -  []  250.56 192.32 0 top
NOREF#65  -  []  344.09 231.46 90 top
NOREF#66  -  []  334.66 181.23 0 top
NOREF#67  -  []  270.51 239.12 90 top
NOREF#68  -  []  89.44 189.85 0 top
NOREF#69  -  []  81.82 292.7 0 top
NOREF#70  -  []  213.39 183.61 0 top
NOREF#71  -  []  263.09 234.38 0 top
NOREF#72  -  []  215.38 182.3 90 top
NOREF#73  -  []  0 0 90 top
NOREF#74  -  []  122.64 246.5 90 top
NOREF#75  -  []  119.44 154.45 0 top
NOREF#76  -  []  121.19 158.1 0 top
NOREF#77  -  []  227.64 182.03 0 top
NOREF#78  -  []  350.83 238.82 0 top
NOREF#79  -  []  324.38 213.87 0 top
NOREF#80  -  []  236.52 133.3 0 top
NOREF#81  -  []  267.41 134.7 0 top
NOREF#82  -  []  307.05 134.31 0 top
NOREF#83  -  []  348.22 242.08 90 top
NOREF#84  -  []  308.57 244.96 0 top
NOREF#85  -  []  112.42 136.82 0 top
NOREF#86  -  []  39.86 255.11 0 top
NOREF#87  -  []  290.61 235.6 90 top
NOREF#88  -  []  276.24 417.57 90 top
NOREF#89  -  []  268.26 222.94 90 top
NOREF#90  -  []  271.15 250.18 90 top
NOREF#91  -  []  469.35 151.25 90 top
NOREF#92  -  []  226.94 264.26 0 top
NOREF#93  -  []  224.09 231.46 90 top
NOREF#94  -  []  102.08 173.3 0 top
NOREF#95  -  []  83.2 262.88 90 top
NOREF#96  -  []  468.1 186.2 0 top
NOREF#97  -  []  350.5 250.18 90 top
NOREF#98  -  []  227.91 244.36 90 top
NOREF#99  -  []  284.79 271.56 90 top
NOREF#100  -  []  291.64 255.18 0 top
NOREF#101  -  []  309.33 210.27 0 top
NOREF#102  -  []  121.19 189.85 0 top
NOREF#103  -  []  539.65 193.24 0 top
NOREF#104  -  []  351.8 250.18 90 top
NOREF#105  -  []  322.64 267.56 0 top
NOREF#106  -  []  115.04 186.2 0 top
NOREF#107  -  []  254.66 252.79 0 top
NOREF#108  -  []  335.56 240.9 90 top
NOREF#109  -  []  311.16 185.61 0 top
NOREF#110  -  []  130.05 285.46 90 top
NOREF#111  -  []  270.83 244.63 0 top
NOREF#112  -  []  215.83 259.63 0 top
NOREF#113  -  []  350.54 184.96 0 top
NOREF#114  -  []  339.41 166.69 0 top
NOREF#115  -  []  225.96 248.85 0 top
NOREF#116  -  []  351.48 240.02 0 top
NOREF#117  -  []  255.56 192.47 90 top
NOREF#118  -  []  232.16 181.38 0 top
NOREF#119  -  []  290.61 180.7 0 top
NOREF#120  -  []  270.18 243.37 0 top
NOREF#121  -  []  95.99 154.45 0 top
NOREF#122  -  []  335.06 243.2 0 top
NOREF#123  -  []  487.94 138.68 0 top
NOREF#124  -  []  38.35 196.2 0 top
NOREF#125  -  []  350.83 191.08 0 top
NOREF#126  -  []  483 154.45 0 top
NOREF#127  -  []  478.68 143.87 0 top
NOREF#128  -  []  503.64 224.01 0 top
NOREF#129  -  []  311.48 191.08 0 top
NOREF#130  -  []  215.14 18.41 0 top
NOREF#131  -  []  480.8 249.7 0 top
NOREF#132  -  []  553.49 149.79 90 top
NOREF#133  -  []  314.65 183.33 90 top
NOREF#134  -  []  314.91 163.58 90 top
NOREF#135  -  []  503.5 223.29 90 top
NOREF#136  -  []  293.99 193.86 90 top
NOREF#137  -  []  349.25 134 0 top
NOREF#138  -  []  314.44 146.64 0 top
NOREF#139  -  []  320.81 208.22 90 top
NOREF#140  -  []  348.25 173.12 90 top
NOREF#141  -  []  285.73 274.51 0 top
NOREF#142  -  []  259.33 196.13 0 top
NOREF#143  -  []  264.52 283.89 90 top
NOREF#144  -  []  232.23 230.19 90 top
NOREF#145  -  []  265.14 295.18 90 top
NOREF#146  -  []  213.54 239.12 90 top
NOREF#147  -  []  310.13 268.11 90 top
NOREF#148  -  []  270.84 243.37 90 top
NOREF#149  -  []  546.66 210.41 90 top
NOREF#150  -  []  327.07 208.22 90 top
NOREF#151  -  []  351.08 209.73 0 top
NOREF#152  -  []  350.51 179.12 90 top
NOREF#153  -  []  272.2 283.17 90 top
NOREF#154  -  []  95.31 229.22 90 top
NOREF#155  -  []  348.23 178.18 0 top
NOREF#156  -  []  228.27 184.64 90 top
NOREF#157  -  []  277.27 267.24 90 top
NOREF#158  -  []  487.64 204.4 90 top
NOREF#159  -  []  116.29 214.75 90 top
NOREF#160  -  []  311.81 241.72 90 top
NOREF#161  -  []  450.05 189.85 0 top
NOREF#162  -  []  294.36 241.55 0 top
NOREF#163  -  []  229.59 245.93 90 top
NOREF#164  -  []  352.15 181.38 0 top
NOREF#165  -  []  365.83 229.63 90 top
NOREF#166  -  []  349.85 244.32 90 top
NOREF#167  -  []  331.64 183.61 0 top
NOREF#168  -  []  231.84 184.96 0 top
NOREF#169  -  []  333.22 250.39 90 top
NOREF#170  -  []  333.22 178.82 90 top
NOREF#171  -  []  307.56 144.79 0 top
NOREF#172  -  []  352.13 180.12 0 top
NOREF#173  -  []  485.78 227.57 90 top
NOREF#174  -  []  316.37 207.56 0 top
NOREF#175  -  []  455.4 154.45 0 top
NOREF#176  -  []  230.19 238.82 0 top
NOREF#177  -  []  236.37 267.56 0 top
NOREF#178  -  []  245.58 273.87 90 top
NOREF#179  -  []  310.5 241.72 90 top
NOREF#180  -  []  213.61 182 90 top
NOREF#181  -  []  294.66 241.23 0 top
NOREF#182  -  []  315.91 163.58 90 top
NOREF#183  -  []  88.89 156.45 0 top
NOREF#184  -  []  325.4 212.03 90 top
NOREF#185  -  []  299.42 292.84 90 top
NOREF#186  -  []  210.61 180.7 0 top
NOREF#187  -  []  312.78 243.4 90 top
NOREF#188  -  []  270.24 184.64 90 top
NOREF#189  -  []  223.71 288.4 0 top
NOREF#190  -  []  225.68 185.29 90 top
NOREF#191  -  []  456.65 151.25 90 top
NOREF#192  -  []  211.96 193.56 90 top
NOREF#193  -  []  211.34 254.86 0 top
NOREF#194  -  []  308.27 185.93 0 top
NOREF#195  -  []  252.01 254.76 0 top
NOREF#196  -  []  269.59 185.29 90 top
NOREF#197  -  []  312.78 249.88 90 top
NOREF#198  -  []  223.71 285.98 90 top
NOREF#199  -  []  273.4 294.56 0 top
NOREF#200  -  []  273.99 208.8 90 top
NOREF#201  -  []  333.66 254.76 0 top
NOREF#202  -  []  227.05 133.3 90 top
NOREF#203  -  []  330.61 180.7 0 top
NOREF#204  -  []  228.66 226.14 0 top
NOREF#205  -  []  293.09 243.29 90 top
NOREF#206  -  []  215.83 229.63 90 top
NOREF#207  -  []  210.61 192.27 0 top
NOREF#208  -  []  357.14 146.64 90 top
NOREF#209  -  []  276.29 269.73 0 top
NOREF#210  -  []  312.14 182.07 90 top
NOREF#211  -  []  307.58 184.06 90 top
NOREF#212  -  []  227.91 238.48 90 top
NOREF#213  -  []  343.27 175.18 0 top
NOREF#214  -  []  237.95 143.53 90 top
NOREF#215  -  []  269.25 134 0 top
NOREF#216  -  []  213.1 190.39 90 top
NOREF#217  -  []  345.33 134.7 0 top
NOREF#218  -  []  355.44 254.76 90 top
NOREF#219  -  []  255.06 194.76 0 top
NOREF#220  -  []  332.78 239.12 90 top
NOREF#221  -  []  316.65 207.92 90 top
NOREF#222  -  []  547.04 220.95 90 top
NOREF#223  -  []  275.12 294.17 0 top
NOREF#224  -  []  370.33 162.13 90 top
NOREF#225  -  []  546.66 207.62 90 top
NOREF#226  -  []  214.68 255.18 0 top
NOREF#227  -  []  350.5 190.18 90 top
NOREF#228  -  []  214.68 242.3 90 top
NOREF#229  -  []  290.61 240.7 0 top
NOREF#230  -  []  474.45 186.2 0 top
NOREF#231  -  []  223.71 288.65 90 top
NOREF#232  -  []  230.18 243.37 90 top
NOREF#233  -  []  267.25 234.3 90 top
NOREF#234  -  []  267.9 244.36 90 top
NOREF#235  -  []  356.07 207.24 0 top
NOREF#236  -  []  539.84 233.03 90 top
NOREF#237  -  []  90.79 241.07 0 top
NOREF#238  -  []  282.91 207.92 0 top
NOREF#239  -  []  358.39 139.82 0 top
NOREF#240  -  []  270.5 241.72 90 top
NOREF#241  -  []  364.79 271.56 0 top
NOREF#242  -  []  215.01 182 90 top
NOREF#243  -  []  355.08 183 0 top
NOREF#244  -  []  213.66 254.76 0 top
NOREF#245  -  []  352.78 191.08 0 top
NOREF#246  -  []  104.54 154.45 0 top
NOREF#247  -  []  272.14 191.08 0 top
NOREF#248  -  []  223.27 233.14 0 top
NOREF#249  -  []  354.75 282.62 90 top
NOREF#250  -  []  313.46 243.33 0 top
NOREF#251  -  []  293.1 178.82 90 top
NOREF#252  -  []  265.06 166.14 0 top
NOREF#253  -  []  276.65 207.92 0 top
NOREF#254  -  []  345.48 175.27 0 top
NOREF#255  -  []  213.99 182.3 90 top
NOREF#256  -  []  502.15 205.6 90 top
NOREF#257  -  []  90.79 132.82 90 top
NOREF#258  -  []  309.23 181.06 0 top
NOREF#259  -  []  0 0 0 top
NOREF#260  -  []  211.16 187.72 90 top
NOREF#261  -  []  228.27 185.93 0 top
NOREF#262  -  []  351.11 293.99 90 top
NOREF#263  -  []  254.68 193.86 90 top
NOREF#264  -  []  284.79 211.56 0 top
NOREF#265  -  []  309.23 208.44 0 top
NOREF#266  -  []  312.06 245.29 90 top
NOREF#267  -  []  231.84 186.26 0 top
NOREF#268  -  []  312.06 185.29 90 top
NOREF#269  -  []  269.89 186.26 0 top
NOREF#270  -  []  232.14 180.12 90 top
NOREF#271  -  []  223.09 234.94 0 top
NOREF#272  -  []  316.47 269.49 0 top
NOREF#273  -  []  109.42 228.97 90 top
NOREF#274  -  []  213.09 254.86 90 top
NOREF#275  -  []  347.9 182.38 90 top
NOREF#276  -  []  294.31 253.56 90 top
NOREF#277  -  []  309.53 184.02 0 top
NOREF#278  -  []  226.97 185.94 90 top
NOREF#279  -  []  304.52 286.56 90 top
NOREF#280  -  []  322.56 209.73 0 top
NOREF#281  -  []  333.39 243.61 0 top
NOREF#282  -  []  219.72 293.16 0 top
NOREF#283  -  []  260.66 166.14 0 top
NOREF#284  -  []  270.84 238.82 0 top
NOREF#285  -  []  276.52 133.3 0 top
NOREF#286  -  []  311.49 242.62 0 top
NOREF#287  -  []  315.12 295.18 90 top
NOREF#288  -  []  352.2 283.17 90 top
NOREF#289  -  []  95.99 217.95 0 top
NOREF#290  -  []  331.31 183.2 0 top
NOREF#291  -  []  351.54 184.64 0 top
NOREF#292  -  []  309.59 245.93 0 top
NOREF#293  -  []  233.34 270 0 top
NOREF#294  -  []  272.13 241.42 90 top
NOREF#295  -  []  310.84 242.62 0 top
NOREF#296  -  []  306.6 179.76 90 top
NOREF#297  -  []  272.23 170.19 90 top
NOREF#298  -  []  276.52 133.3 90 top
NOREF#299  -  []  245.1 208.22 0 top
NOREF#300  -  []  229.59 246.58 90 top
NOREF#301  -  []  241.44 250.47 0 top
NOREF#302  -  []  352.15 241.38 0 top
NOREF#303  -  []  223.95 173.82 90 top
NOREF#304  -  []  456.64 232.66 90 top
NOREF#305  -  []  305.95 188.86 0 top
NOREF#306  -  []  456.55 196.32 90 top
NOREF#307  -  []  274.74 251.08 0 top
NOREF#308  -  []  255.58 183.29 90 top
NOREF#309  -  []  115.04 186.2 0 top
NOREF#310  -  []  347.58 244.06 0 top
NOREF#311  -  []  230.84 238.82 90 top
NOREF#312  -  []  284.68 214.19 0 top
NOREF#313  -  []  314.75 282.62 90 top
NOREF#314  -  []  210.56 235.55 90 top
NOREF#315  -  []  348.66 226.14 0 top
NOREF#316  -  []  353.99 208.8 90 top
NOREF#317  -  []  230.18 191.08 0 top
NOREF#318  -  []  310.18 183.37 0 top
NOREF#319  -  []  269.59 245.29 90 top
NOREF#320  -  []  348.23 238.18 0 top
NOREF#321  -  []  543.62 154.99 0 top
NOREF#322  -  []  254.36 253.12 0 top
NOREF#323  -  []  346.06 146.65 90 top
NOREF#324  -  []  498.93 224.51 0 top
NOREF#325  -  []  226.94 204.26 0 top
NOREF#326  -  []  269.53 178.82 0 top
NOREF#327  -  []  316.23 134 90 top
NOREF#328  -  []  349.53 238.82 90 top
NOREF#329  -  []  294.68 193.86 90 top
NOREF#330  -  []  237.71 207.75 0 top
NOREF#331  -  []  303.09 234.38 0 top
NOREF#332  -  []  215.83 259.63 0 top
NOREF#333  -  []  233.63 143.53 0 top
NOREF#334  -  []  84.1 265.34 0 top
NOREF#335  -  []  122.18 233.93 0 top
NOREF#336  -  []  274.91 163.58 90 top
NOREF#337  -  []  112.42 232.07 90 top
NOREF#338  -  []  229.53 244.02 90 top
NOREF#339  -  []  231.15 250.18 90 top
NOREF#340  -  []  270.82 249.88 90 top
NOREF#341  -  []  339.41 226.69 0 top
NOREF#342  -  []  293.22 250.39 90 top
NOREF#343  -  []  312.46 190.18 90 top
NOREF#344  -  []  339.42 293.48 0 top
NOREF#345  -  []  226.93 189.88 90 top
NOREF#346  -  []  363.15 211.05 0 top
NOREF#347  -  []  231.08 269.73 0 top
NOREF#348  -  []  275.44 254.76 90 top
NOREF#349  -  []  244.79 271.56 0 top
NOREF#350  -  []  364.79 271.56 90 top
NOREF#351  -  []  355.44 194.76 90 top
NOREF#352  -  []  346.6 250.18 90 top
NOREF#353  -  []  322.91 207.92 0 top
NOREF#354  -  []  232.79 183.41 0 top
NOREF#355  -  []  231.55 285.02 0 top
NOREF#356  -  []  84.29 221.6 0 top
NOREF#357  -  []  102.34 186.2 0 top
NOREF#358  -  []  327.4 207.92 90 top
NOREF#359  -  []  259.41 226.69 0 top
NOREF#360  -  []  295.71 242 90 top
NOREF#361  -  []  353.75 243.65 0 top
NOREF#362  -  []  271.54 185.94 90 top
NOREF#363  -  []  306.91 144.24 90 top
NOREF#364  -  []  253.22 251.59 0 top
NOREF#365  -  []  289.83 263.63 90 top
NOREF#366  -  []  321.44 190.47 0 top
NOREF#367  -  []  343.95 232.9 90 top
NOREF#368  -  []  335.01 242 90 top
NOREF#369  -  []  223.71 283.32 90 top
NOREF#370  -  []  303.09 174.38 0 top
NOREF#371  -  []  354.91 163.58 0 top
NOREF#372  -  []  334.36 193.12 0 top
NOREF#373  -  []  348.26 162.94 90 top
NOREF#374  -  []  82.01 288.17 90 top
NOREF#375  -  []  308.27 245.93 0 top
NOREF#376  -  []  473.7 188.2 0 top
NOREF#377  -  []  270.73 166.09 90 top
NOREF#378  -  []  551.91 164.1 0 top
NOREF#379  -  []  233.17 291.16 90 top
NOREF#380  -  []  351.8 239.12 90 top
NOREF#381  -  []  254.38 254.86 0 top
NOREF#382  -  []  305.83 145.8 90 top
NOREF#383  -  []  271.84 184.96 0 top
NOREF#384  -  []  120.02 164.07 90 top
NOREF#385  -  []  255.71 182 90 top
NOREF#386  -  []  356.97 208.22 90 top
NOREF#387  -  []  236.29 209.25 90 top
NOREF#388  -  []  87.69 154.45 0 top
NOREF#389  -  []  344.96 135.33 0 top
NOREF#390  -  []  101.59 251.7 0 top
NOREF#391  -  []  306.97 185.94 90 top
NOREF#392  -  []  222.95 286.63 90 top
NOREF#393  -  []  267.77 233.98 0 top
NOREF#394  -  []  215.38 253.86 90 top
NOREF#395  -  []  352.74 184.64 90 top
NOREF#396  -  []  90.88 232.66 0 top
NOREF#397  -  []  213.22 238.82 90 top
NOREF#398  -  []  114.42 202.82 0 top
NOREF#399  -  []  229.59 245.93 0 top
NOREF#400  -  []  306.06 146.65 90 top
NOREF#401  -  []  230.18 242.62 0 top
NOREF#402  -  []  224.52 286.56 90 top
NOREF#403  -  []  313.35 241.38 90 top
NOREF#404  -  []  106.74 186.2 0 top
NOREF#405  -  []  269.5 208.8 90 top
NOREF#406  -  []  276.97 268.22 90 top
NOREF#407  -  []  235.44 254.76 90 top
NOREF#408  -  []  309.53 238.82 0 top
NOREF#409  -  []  310.19 178.82 90 top
NOREF#410  -  []  272.12 189.88 90 top
NOREF#411  -  []  230.51 179.12 90 top
NOREF#412  -  []  331.34 254.86 0 top
NOREF#413  -  []  541.25 149.79 90 top
NOREF#414  -  []  267.94 181.06 0 top
NOREF#415  -  []  267.25 178.48 90 top
NOREF#416  -  []  83.2 290.32 90 top
NOREF#417  -  []  266.93 249.88 90 top
NOREF#418  -  []  361.04 135.78 0 top
NOREF#419  -  []  315.48 294.56 0 top
NOREF#420  -  []  253.09 254.86 90 top
NOREF#421  -  []  213.29 253.86 90 top
NOREF#422  -  []  349.15 270.51 0 top
NOREF#423  -  []  215.71 193.56 90 top
NOREF#424  -  []  312.13 178.82 90 top
NOREF#425  -  []  231.16 179.12 90 top
NOREF#426  -  []  347.25 233.9 90 top
NOREF#427  -  []  212.45 250.39 0 top
NOREF#428  -  []  243.15 271.05 0 top
NOREF#429  -  []  230.89 183.33 0 top
NOREF#430  -  []  323.45 271.37 0 top
NOREF#431  -  []  346.94 264.26 0 top
NOREF#432  -  []  498.63 224.19 0 top
NOREF#433  -  []  270.54 180.4 0 top
NOREF#434  -  []  268.93 240.73 0 top
NOREF#435  -  []  423.56 417.57 90 top
NOREF#436  -  []  230.73 166.09 0 top
NOREF#437  -  []  314.61 294.17 90 top
NOREF#438  -  []  456.64 169.16 0 top
NOREF#439  -  []  270.86 185.29 0 top
NOREF#440  -  []  325.73 273.87 90 top
NOREF#441  -  []  268.01 233.3 90 top
NOREF#442  -  []  234.44 138.77 0 top
NOREF#443  -  []  271.48 181.42 90 top
NOREF#444  -  []  231.54 185.94 90 top
NOREF#445  -  []  353.34 210 0 top
NOREF#446  -  []  570 149.79 90 top
NOREF#447  -  []  280.81 158.16 90 top
NOREF#448  -  []  566.06 170.72 0 top
NOREF#449  -  []  347.64 181.38 90 top
NOREF#450  -  []  231.84 244.96 0 top
NOREF#451  -  []  566.42 171.11 0 top
NOREF#452  -  []  307.77 174.98 0 top
NOREF#453  -  []  304.52 285.16 0 top
NOREF#454  -  []  227.75 175.77 0 top
NOREF#455  -  []  250.61 175.6 90 top
NOREF#456  -  []  238.33 268.22 90 top
NOREF#457  -  []  253.66 183.2 0 top
NOREF#458  -  []  42.76 297.45 90 top
NOREF#459  -  []  228.93 180.73 0 top
NOREF#460  -  []  311.44 240.08 90 top
NOREF#461  -  []  252.45 190.39 0 top
NOREF#462  -  []  340.33 249.91 0 top
NOREF#463  -  []  295.38 193.86 90 top
NOREF#464  -  []  85.49 217.95 0 top
NOREF#465  -  []  350.89 182.68 90 top
NOREF#466  -  []  231.19 243 0 top
NOREF#467  -  []  275.08 243 0 top
NOREF#468  -  []  291.64 242.3 90 top
NOREF#469  -  []  360.04 140.12 0 top
NOREF#470  -  []  114.42 171.07 0 top
NOREF#471  -  []  213.1 250.39 90 top
NOREF#472  -  []  225.43 292.08 90 top
NOREF#473  -  []  107.94 156.45 0 top
NOREF#474  -  []  365.4 212.03 90 top
NOREF#475  -  []  232.78 249.88 90 top
NOREF#476  -  []  546.66 208.27 0 top
NOREF#477  -  []  311.81 181.72 90 top
NOREF#478  -  []  210.56 247.12 90 top
NOREF#479  -  []  356.23 163.88 90 top
NOREF#480  -  []  235.08 183 0 top
NOREF#481  -  []  98.19 217.95 0 top
NOREF#482  -  []  102.34 249.7 0 top
NOREF#483  -  []  255.01 182 90 top
NOREF#484  -  []  334.68 183.61 0 top
NOREF#485  -  []  290.56 247.12 90 top
NOREF#486  -  []  351.8 190.18 90 top
NOREF#487  -  []  315.38 249.88 90 top
NOREF#488  -  []  568.42 164.1 0 top
NOREF#489  -  []  461.55 158.1 0 top
NOREF#490  -  []  330.56 240.75 0 top
NOREF#491  -  []  303.09 173.82 0 top
NOREF#492  -  []  357.95 146.07 90 top
NOREF#493  -  []  349.59 245.93 90 top
NOREF#494  -  []  333.54 250.69 90 top
NOREF#495  -  []  90.88 137.41 90 top
NOREF#496  -  []  266.94 204.26 0 top
NOREF#497  -  []  211.64 242.3 90 top
